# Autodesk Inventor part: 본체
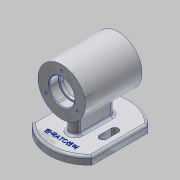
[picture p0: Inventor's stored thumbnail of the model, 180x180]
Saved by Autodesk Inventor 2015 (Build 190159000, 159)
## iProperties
Created: 2022-02
Part Number: 본체
Material: 알루미늄 6061
Document SubType Name: Modeling
Designer: 학생용
Density: 2.7 g/cm^3
Appearance: 알루미늄 - 평지
Mass: 494.598 g
Surface Area: 487.287 cm^2
Volume: 183.184 cm^3
Author: 학생용
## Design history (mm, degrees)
sketch "스케치1"
  geometry: C1 r 30 at (0, 0); 1 further point
  constraints: 1 centre point, 1 coincident
  dimensions: "d0" = 60 diameter of C1
extrude "돌출1" new body sketch "스케치1" distance "d1" = 72; taper "d2" = 0 deg
sketch "스케치2"
  geometry: C1 r 16 at (0, 0); 1 further point
  constraints: 1 centre point, 1 coincident
  dimensions: "d3" = 32 diameter of C1
extrude "돌출2" cut sketch "스케치2" distance "d4" = 12; taper "d5" = 0 deg
sketch "스케치3"
  geometry: C1 r 14 at (0, 0); 1 further point
  constraints: 1 centre point, 1 coincident
  dimensions: "d6" = 28 diameter of C1
extrude "돌출3" cut sketch "스케치3" distance "d7" = 4; taper "d8" = 0 deg
sketch "스케치4"
  geometry: C1 r 25 at (0, 0); 1 further point
  constraints: 1 centre point, 1 coincident
  dimensions: "d9" = 50 diameter of C1
extrude "돌출4" cut sketch "스케치4" distance "d10" = 40; taper "d11" = 0 deg
sketch "스케치5"
  geometry: C1 r 16 at (0, 0); 1 further point
  constraints: 1 centre point, 1 coincident
  dimensions: "d12" = 32 diameter of C1
extrude "돌출5" cut sketch "스케치5" distance "d13" = 12; taper "d14" = 0 deg
sketch "스케치6"
  geometry: C1 r 14 at (0, 0); 1 further point
  constraints: 1 centre point, 1 coincident
  dimensions: "d15" = 28 diameter of C1
extrude "돌출6" cut sketch "스케치6" distance "d16" = 4; taper "d17" = 0 deg
chamfer "모따기1" distance "d18" = 1; stored, may be unused: second distance "d19" = 2, angle "d20" = 45 deg
fillet "모깎기1" dims "d21" = 3
fillet "모깎기2" dims "d22" = 0.3
sketch "스케치7" dims "d23" = 46
  geometry: L1 (0, 0)-(0, 23.246); 2 further points
  constraints: 2 end point, 1 coincident, 1 point on line, 1 vertical, 1 vertical alignment, 2 other
hole "구멍1" sketch "스케치7" at (0, 23) diameter "d24" = 3.242; stored, may be unused: countersink angle "d28" = 90 deg, drill point angle "d30" = 118 deg; dims "d25" = 8, "d26" = 4, "d27" = 2, "d29" = 10
sketch "스케치8" dims "d34" = 46
  geometry: L1 (0, 0)-(0, -23); C1 r 1.621 at (0, -23) reference; 2 further points
  constraints: 2 coincident, 2 end point, 1 vertical, 1 vertical alignment, 2 other
hole "구멍2" sketch "스케치8" at (0, -23) diameter "d35" = 3.242; stored, may be unused: countersink angle "d39" = 90 deg, drill point angle "d41" = 118 deg; dims "d36" = 8, "d37" = 4, "d38" = 2, "d40" = 10
node "작업 평면1"
sketch "스케치9"
  geometry: L1 (-30, 0)-(30, 0) reference; L2 (30, 72)-(-30, 72) reference; L3 (-31.853, 36)-(31.853, 36); L4 (-31.85, -5.104)-(31.85, -5.104); L5 (38, 0.504)-(38, 71.496); L6 (31.85, 77.104)-(-31.85, 77.104); L7 (-38, 71.496)-(-38, 0.504); L8 (-35.299, -2.183)-(38, 77.104); L9 (44.15, -5.104)-(-37.791, 71.184); L10 (0, 0)-(0, 72); A1 r 52 centre (0, 36) between (-38, 0.504) and (38, 0.504); A2 r 52 centre (0, 36) between (38, 71.496) and (-38, 71.496)
  constraints: 16 end point, 9 point on circle, 2 centre point, 2 horizontal, 2 midpoint, 2 parallel, 2 point on line, 1 perpendicular, 1 vertical alignment
  dimensions: "d47" = 36 distance between parallel lines of L2 L3; "d50" = 52 radius of A2; "d51" = 52 radius of A1; "d52" = 76 distance between parallel lines of L5 L7; "d53" = 38 distance between parallel lines of L10 L7
extrude "돌출7" join sketch "스케치9" distance "d54" = 10; taper "d55" = 0 deg
sketch "스케치10"
  geometry: L1 (0, 17)-(0, 55); L2 (7, 17)-(7, 55); L3 (-7, 55)-(-7, 17); L4 (30, 72)-(-30, 72) reference; A1 r 7 centre (0, 17) between (-7, 17) and (7, 17); A2 r 7 centre (0, 55) between (7, 55) and (-7, 55); 2 further points
  constraints: 8 end point, 4 point on circle, 4 tangent, 2 centre point, 1 midpoint, 1 parallel, 1 vertical
  dimensions: "d56" = 14 distance between parallel lines of L2 L3; "d57" = 38 distance of L1.end L1.start; "d58" = 36 distance of point (0, 36) point (0, 0); "d59" = 36 distance from line of L4 point (0, 36)
extrude "돌출8" join sketch "스케치10" stored distance "d60" = 10; taper "d61" = 0 deg
sketch "스케치11"
  geometry: L1 (-24, 28.5)-(-24, 43.5); L2 (-19.5, 28.5)-(-19.5, 43.5); L3 (-28.5, 43.5)-(-28.5, 28.5); L4 (-30, 0)-(30, 0) reference; L5 (30, 72)-(-30, 72) reference; L6 (-24, 36)-(24, 36); L7 (0, 0)-(0, 72); L8 (24, 28.5)-(24, 43.5); L9 (19.5, 28.5)-(19.5, 43.5); L10 (28.5, 43.5)-(28.5, 28.5); A1 r 4.5 centre (-24, 28.5) between (-28.5, 28.5) and (-19.5, 28.5); A2 r 4.5 centre (-24, 43.5) between (-19.5, 43.5) and (-28.5, 43.5); A3 r 4.5 centre (24, 28.5) between (19.5, 28.5) and (28.5, 28.5); A4 r 4.5 centre (24, 43.5) between (28.5, 43.5) and (19.5, 43.5); 1 further point
  constraints: 20 end point, 8 point on circle, 8 tangent, 4 centre point, 3 midpoint, 2 parallel, 2 vertical, 1 coincident
  dimensions: "d62" = 9 distance between parallel lines of L2 L3; "d64" = 15 distance of L1.end L1.start; "d66" = 36 vertical distance of L6.start L7.start; "d68" = 36 vertical distance of L6.end L7.start; "d69" = 9 distance between parallel lines of L10 L9; "d70" = 15 distance of L8.end L8.start; "d80" = 48 distance of L6.end L6.start; "d81" = 24 distance from line of L6.end L7
extrude "돌출9" cut sketch "스케치11" stored distance "d71" = 10; taper "d72" = 0 deg
node "작업 평면2"
fillet "모깎기3" dims "d74" = 3
sketch "스케치12"
  geometry: L1 (-30, 0)-(30, 0) reference; C1 r 42.5 at (0, 36); 1 further point
  constraints: 1 centre point, 1 midpoint, 1 vertical alignment, 1 other
  dimensions: "d76" = 85 diameter of C1; "d77" = 36 distance from line of C1.centre L1
extrude "돌출10" join sketch "스케치12" distance "d78" = 0.5; taper "d79" = 0 deg
node "솔리드1"
pattern_circular "원형 패턴1" dims angle "d32" = 360 deg
pattern_circular "원형 패턴2" dims angle "d43" = 360 deg
other parameters: "d45" = -62, "d46" = 104, "d73" = 0
